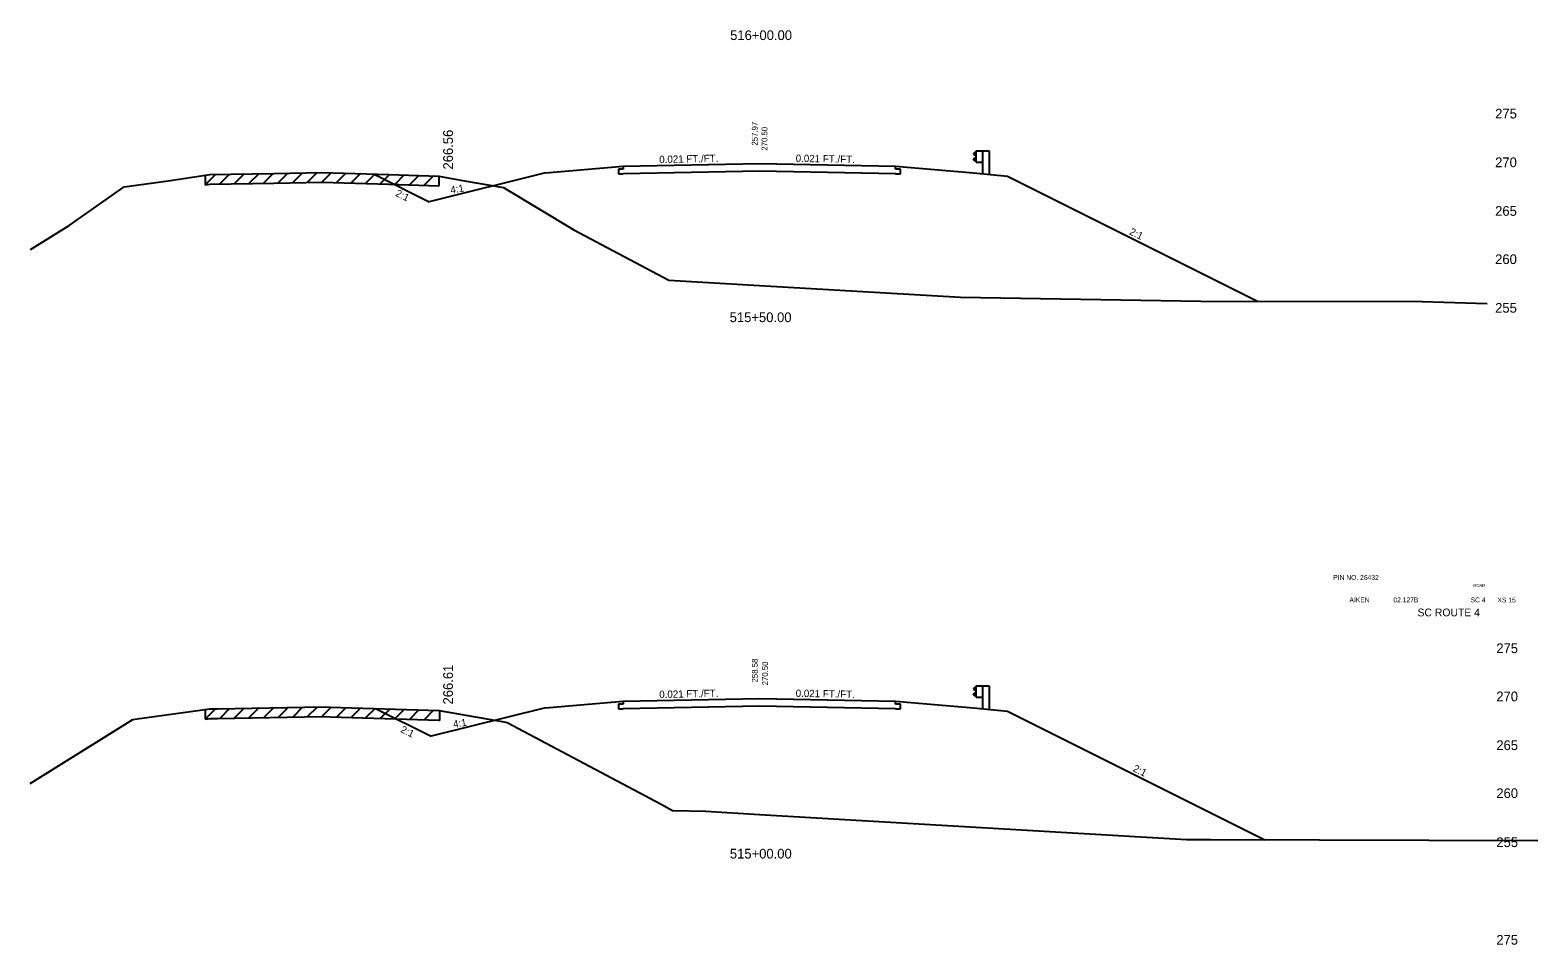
# Model space of a CAD drawing. Extents: x 883 to 1160, y 1002 to 4323.
# Drawn here: x 1005 to 1160, y 2675.2 to 2769.2 of the extents above; entities that cross this region are included whole.
import ezdxf

# ---------------------------------------------------------------- set-up
doc = ezdxf.new("R2010")
doc.units = 0
for name, color, linetype in [('Level 1', 7, 'Continuous'), ('Level 10', 7, 'Continuous'), ('Level 11', 7, 'Continuous'), ('Level 12', 7, 'Continuous'), ('Level 24', 7, 'Continuous'), ('Level 3', 7, 'Continuous'), ('Level 32', 7, 'Continuous'), ('Level 33', 7, 'Continuous'), ('Level 59', 7, 'Continuous'), ('Level 6', 7, 'Continuous'), ('Level 60', 7, 'Continuous'), ('Level 61', 7, 'Continuous'), ('Level 7', 7, 'Continuous')]:
    doc.layers.add(name, color=color, linetype=linetype)

msp = doc.modelspace()

# ---------------------------------------------------------------- linework, layer by layer
at = {"layer": 'Level 11'}
for p, q in [((1066, 2755.21), (1066, 2754.91)), ((1094, 2754.91), (1094, 2755.21)), ((1066, 2754.91), (1065.5, 2754.9)), ((1065.5, 2754.9), (1065.5, 2754.42)), ((1065.5, 2754.42), (1066, 2754.43)), ((1094.5, 2754.9), (1094, 2754.91)), ((1094, 2754.43), (1094.5, 2754.42)), ((1094.5, 2754.42), (1094.5, 2754.9)), ((1066, 2699.91), (1065.5, 2699.9)), ((1065.5, 2699.9), (1065.5, 2699.42)), ((1065.5, 2699.42), (1066, 2699.43)), ((1066, 2700.21), (1066, 2699.91)), ((1094, 2699.91), (1094, 2700.21)), ((1094.5, 2699.9), (1094, 2699.91)), ((1094, 2699.43), (1094.5, 2699.42)), ((1094.5, 2699.42), (1094.5, 2699.9))]:
    msp.add_line(p, q, dxfattribs=at)
at = {"layer": 'Level 12'}
for p, q in [((1080, 2754.72), (1066, 2754.43)), ((1094, 2754.43), (1080, 2754.72)), ((1080, 2699.72), (1066, 2699.43)), ((1094, 2699.43), (1080, 2699.72))]:
    msp.add_line(p, q, dxfattribs=at)
at = {"layer": 'Level 24'}
for p, q in [((1102.27, 2756.72), (1102, 2756.52)), ((1102.27, 2755.63), (1102.27, 2756.79)), ((1102.27, 2756.79), (1102.94, 2756.79)), ((1102.94, 2756.79), (1102.94, 2754.45)), ((1102.94, 2756.79), (1103.6, 2756.79)), ((1103.6, 2756.79), (1103.6, 2754.38)), ((1102, 2756.52), (1102, 2756.47)), ((1102, 2756.47), (1102.27, 2756.27)), ((1102, 2755.95), (1102.27, 2756.15)), ((1102, 2755.9), (1102, 2755.95)), ((1102.27, 2755.7), (1102, 2755.9)), ((1102.27, 2755.63), (1102.94, 2755.63)), ((1102.27, 2701.72), (1102, 2701.52)), ((1102, 2701.52), (1102, 2701.47)), ((1102, 2701.47), (1102.27, 2701.27)), ((1102, 2700.95), (1102.27, 2701.15)), ((1102, 2700.9), (1102, 2700.95)), ((1102.27, 2700.7), (1102, 2700.9)), ((1102.27, 2700.63), (1102.27, 2701.79)), ((1102.27, 2701.79), (1102.94, 2701.79)), ((1102.94, 2701.79), (1102.94, 2699.45)), ((1102.94, 2701.79), (1103.6, 2701.79)), ((1103.6, 2701.79), (1103.6, 2699.38)), ((1102.27, 2700.63), (1102.94, 2700.63))]:
    msp.add_line(p, q, dxfattribs=at)
at = {"layer": 'Level 59'}
for p, q in [((1066, 2755.21), (1080, 2755.5)), ((1080, 2755.5), (1094, 2755.21)), ((1066, 2700.21), (1080, 2700.5)), ((1080, 2700.5), (1094, 2700.21))]:
    msp.add_line(p, q, dxfattribs=at)
at = {"layer": 'Level 6'}
for p, q in [((1058, 2754.54), (1066, 2755.21)), ((1094, 2755.21), (1102, 2754.54)), ((1102, 2754.54), (1105.5, 2754.19)), ((1058, 2699.54), (1066, 2700.21)), ((1094, 2700.21), (1102, 2699.54)), ((1102, 2699.54), (1105.5, 2699.19))]:
    msp.add_line(p, q, dxfattribs=at)
at = {"layer": 'Level 60'}
for p, q in [((1014.7, 2753.11), (1019.25, 2753.73)), ((1019.25, 2753.73), (1023.53, 2754.36)), ((1023.53, 2754.36), (1030.1, 2754.48)), ((1030.1, 2754.48), (1035.01, 2754.58)), ((1035.01, 2754.58), (1041.91, 2754.37)), ((1041.91, 2754.37), (1047.06, 2754.2)), ((1047.06, 2754.2), (1049.68, 2753.73)), ((1049.68, 2753.73), (1053.7, 2753.03)), ((1009.06, 2749.12), (1014.7, 2753.11)), ((1053.7, 2753.03), (1060.93, 2748.69)), ((1005.1, 2746.64), (1009.06, 2749.12)), ((1060.93, 2748.69), (1070.69, 2743.52)), ((1070.69, 2743.52), (1080, 2742.97)), ((1080, 2742.97), (1100.67, 2741.75)), ((1100.67, 2741.75), (1125.38, 2741.36)), ((1125.38, 2741.36), (1148.11, 2741.31)), ((1148.11, 2741.31), (1154.8, 2741.11)), ((1016.05, 2698.42), (1023.53, 2699.43)), ((1023.53, 2699.43), (1024.3, 2699.44)), ((1024.3, 2699.44), (1035.03, 2699.63)), ((1035.03, 2699.63), (1035.87, 2699.6)), ((1035.87, 2699.6), (1047.08, 2699.26)), ((1047.08, 2699.26), (1053.57, 2698.13)), ((1005.05, 2691.74), (1015.59, 2698.33)), ((1015.59, 2698.33), (1016.05, 2698.42)), ((1053.57, 2698.13), (1054.08, 2698.01)), ((1054.08, 2698.01), (1069.9, 2689.63)), ((1069.9, 2689.63), (1071.07, 2688.98)), ((1071.07, 2688.98), (1074.5, 2688.91)), ((1074.5, 2688.91), (1080, 2688.58)), ((1080, 2688.58), (1123.89, 2686)), ((1123.89, 2686), (1126.36, 2685.99)), ((1126.36, 2685.99), (1160, 2685.9))]:
    msp.add_line(p, q, dxfattribs=at)
at = {"layer": 'Level 61'}
for p, q in [((1024.11, 2754.37), (1023.02, 2753.29)), ((1023.02, 2754.29), (1023.02, 2753.29)), ((1023.53, 2753.36), (1030.1, 2753.48)), ((1025.54, 2754.4), (1024.52, 2753.38)), ((1027.04, 2754.43), (1026.02, 2753.41)), ((1028.54, 2754.45), (1027.52, 2753.43)), ((1030.04, 2754.48), (1029.02, 2753.46)), ((1030.1, 2753.48), (1035.01, 2753.58)), ((1031.54, 2754.51), (1030.52, 2753.49)), ((1033.04, 2754.54), (1032.02, 2753.52)), ((1034.54, 2754.57), (1033.52, 2753.55)), ((1035.01, 2753.58), (1041.91, 2753.37)), ((1035.99, 2754.55), (1035.02, 2753.58)), ((1037.49, 2754.51), (1036.52, 2753.54)), ((1038.99, 2754.46), (1038.02, 2753.49)), ((1040.49, 2754.41), (1039.52, 2753.44)), ((1041.99, 2754.37), (1041.02, 2753.4)), ((1043.49, 2754.32), (1042.52, 2753.35)), ((1044.99, 2754.27), (1044.02, 2753.3)), ((1046.49, 2754.22), (1045.52, 2753.25)), ((1047.1, 2753.19), (1047.1, 2754.19)), ((1023.02, 2753.29), (1023.53, 2753.36)), ((1041.91, 2753.37), (1047.06, 2753.2)), ((1047.06, 2753.2), (1047.1, 2753.19)), ((1024.11, 2699.44), (1023.03, 2698.36)), ((1023.03, 2699.36), (1023.03, 2698.36)), ((1025.55, 2699.46), (1024.53, 2698.45)), ((1027.05, 2699.49), (1026.03, 2698.47)), ((1028.55, 2699.52), (1027.53, 2698.5)), ((1030.05, 2699.54), (1029.03, 2698.52)), ((1031.55, 2699.57), (1030.53, 2698.55)), ((1033.05, 2699.59), (1032.03, 2698.58)), ((1034.55, 2699.62), (1033.53, 2698.6)), ((1036, 2699.6), (1035.03, 2698.63)), ((1037.5, 2699.55), (1036.53, 2698.58)), ((1039, 2699.51), (1038.03, 2698.53)), ((1040.5, 2699.46), (1039.53, 2698.49)), ((1042, 2699.41), (1041.03, 2698.44)), ((1043.5, 2699.37), (1042.53, 2698.4)), ((1045, 2699.32), (1044.03, 2698.35)), ((1046.5, 2699.28), (1045.53, 2698.3)), ((1023.03, 2698.36), (1023.53, 2698.43)), ((1023.53, 2698.43), (1024.3, 2698.44)), ((1024.3, 2698.44), (1035.03, 2698.63)), ((1035.03, 2698.63), (1035.87, 2698.6)), ((1035.87, 2698.6), (1047.08, 2698.26)), ((1047.08, 2698.26), (1047.17, 2698.24)), ((1047.17, 2698.24), (1047.17, 2699.24))]:
    msp.add_line(p, q, dxfattribs=at)
at = {"layer": 'Level 7'}
for p, q in [((1040.32, 2754.42), (1046.05, 2751.56)), ((1058, 2754.54), (1046.05, 2751.56)), ((1105.5, 2754.19), (1131.2, 2741.34)), ((1040.55, 2699.46), (1046.25, 2696.61)), ((1058, 2699.54), (1046.25, 2696.61)), ((1105.5, 2699.19), (1131.93, 2685.98))]:
    msp.add_line(p, q, dxfattribs=at)

# ---------------------------------------------------------------- texts
at = {"layer": 'Level 1'}
for s, height, p in [('516+00.00', 1, (1076.99, 2768.19)), ('515+50.00', 1, (1076.94, 2739.19)), ('PIN NO. 26432', 0.5, (1138.97, 2712.69)), ('AIKEN', 0.5, (1140.64, 2710.38)), ('02.127B', 0.5, (1145.15, 2710.38)), ('SC 4', 0.5, (1153.09, 2710.38)), ('XS 15', 0.5, (1155.85, 2710.37)), ('SC ROUTE 4', 0.8, (1147.63, 2708.94)), ('515+00.00', 1, (1076.96, 2684.04))]:
    msp.add_text(s, height=height, dxfattribs=at).set_placement(p)
at = {"layer": 'Level 10'}
for s, p in [('257.97', (1079.82, 2757.34)), ('258.58', (1079.83, 2702.14))]:
    msp.add_text(s, height=0.6, rotation=90, dxfattribs=at).set_placement(p)
at = {"layer": 'Level 3'}
for s, height, p in [(' 275', 1, (1155.24, 2760.13)), (' 270', 1, (1155.24, 2755.12)), (' 265', 1, (1155.24, 2750.12)), (' 260', 1, (1155.24, 2745.16)), (' 255', 1, (1155.24, 2740.16)), ('ROAD', 0.3, (1153.38, 2711.97)), (' 275', 1, (1155.36, 2705.16)), (' 270', 1, (1155.36, 2700.21)), (' 265', 1, (1155.36, 2695.19)), (' 260', 1, (1155.36, 2690.26)), (' 255', 1, (1155.36, 2685.22)), (' 275', 1, (1155.36, 2675.18))]:
    msp.add_text(s, height=height, dxfattribs=at).set_placement(p)
at = {"layer": 'Level 32'}
for s, rotation, p in [('0.021 FT./FT.', 1.1916, (1069.71, 2755.54)), ('0.021 FT./FT.', 358.8084, (1083.72, 2755.67)), ('2:1', 333.435, (1042.53, 2752.2)), ('4:1', 9.4623, (1048.3, 2752.4)), ('2:1', 333.435, (1117.95, 2748.25)), ('0.021 FT./FT.', 1.1916, (1069.71, 2700.54)), ('0.021 FT./FT.', 358.8084, (1083.72, 2700.67)), ('4:1', 9.4623, (1048.58, 2697.47)), ('2:1', 333.435, (1043.04, 2697.07)), ('2:1', 333.435, (1118.32, 2693.06))]:
    msp.add_text(s, height=0.75, rotation=rotation, dxfattribs=at).set_placement(p)
at = {"layer": 'Level 33'}
for s, p in [('266.56', (1048.5, 2754.88)), ('266.61', (1048.5, 2699.88))]:
    msp.add_text(s, height=1, rotation=90, dxfattribs=at).set_placement(p)
at = {"layer": 'Level 59'}
for p in [(1080.82, 2756.59), (1080.88, 2701.62)]:
    msp.add_text(' 270.50', height=0.6, rotation=90, dxfattribs=at).set_placement(p)

doc.saveas('drawing.dxf')
